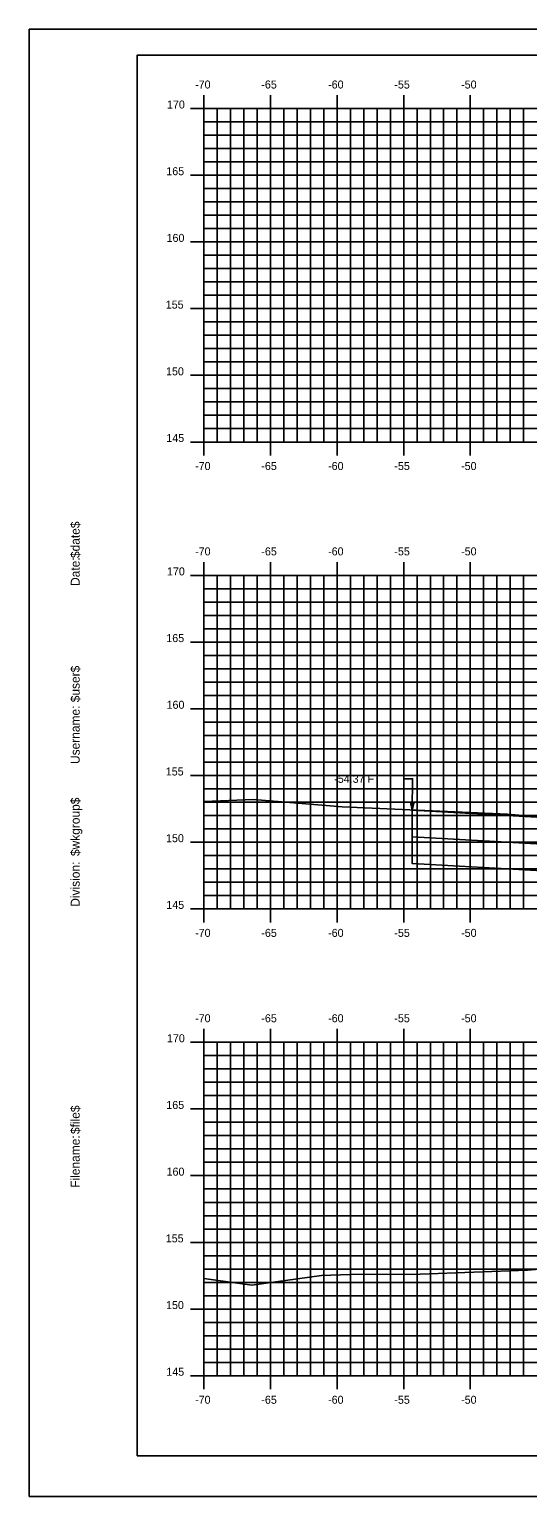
# Model space of a CAD drawing. Extents: x 1141202 to 1141372, y 608981 to 609091.
# Drawn here: x 1141202.4 to 1141239.8, y 608981.3 to 609091.3 of the extents above; entities that cross this region are included whole.
import ezdxf

# ---------------------------------------------------------------- set-up
doc = ezdxf.new("R2010")
doc.units = 0
for name, color, linetype in [('BORDER', 7, 'Continuous'), ('D_Text_Standard', 7, 'Continuous'), ('H_V ANNOTATION', 7, 'Continuous'), ('MAJOR', 7, 'Continuous'), ('MINOR', 7, 'Continuous'), ('PATTERNING', 7, 'Continuous'), ('PLOT BOUNDARY', 7, 'Continuous'), ('S_Roadway_Centerline', 7, 'Continuous')]:
    doc.layers.add(name, color=color, linetype=linetype)

msp = doc.modelspace()

# ---------------------------------------------------------------- linework, layer by layer
at = {"layer": 'BORDER'}
msp.add_lwpolyline([(1141210.51, 608984.34), (1141370.51, 608984.34), (1141370.51, 609089.34), (1141210.51, 609089.34)], close=True, dxfattribs=at)
at = {"layer": 'D_Text_Standard'}
msp.add_lwpolyline([(1141231.14, 609032.75), (1141231.18, 609035.09), (1141230.5, 609035.09)], dxfattribs=at)
msp.add_lwpolyline([(1141231.14, 609032.75), (1141231.01, 609033.34), (1141231.3, 609033.33)], close=True, dxfattribs=at)
at = {"layer": 'MAJOR'}
for p, q in [((1141215.51, 609086.34), (1141215.51, 609085.34)), ((1141220.51, 609086.34), (1141220.51, 609085.34)), ((1141225.51, 609086.34), (1141225.51, 609085.34)), ((1141230.51, 609086.34), (1141230.51, 609085.34)), ((1141235.51, 609086.34), (1141235.51, 609085.34)), ((1141214.51, 609085.34), (1141215.51, 609085.34)), ((1141215.51, 609085.34), (1141355.51, 609085.34)), ((1141215.51, 609060.34), (1141215.51, 609085.34)), ((1141215.51, 609060.34), (1141215.51, 609085.34)), ((1141215.51, 609085.34), (1141355.51, 609085.34)), ((1141220.51, 609060.34), (1141220.51, 609085.34)), ((1141225.51, 609060.34), (1141225.51, 609085.34)), ((1141230.51, 609060.34), (1141230.51, 609085.34)), ((1141235.51, 609060.34), (1141235.51, 609085.34)), ((1141214.51, 609080.34), (1141215.51, 609080.34)), ((1141215.51, 609080.34), (1141355.51, 609080.34)), ((1141214.51, 609075.34), (1141215.51, 609075.34)), ((1141215.51, 609075.34), (1141355.51, 609075.34)), ((1141214.51, 609070.34), (1141215.51, 609070.34)), ((1141215.51, 609070.34), (1141355.51, 609070.34)), ((1141214.51, 609065.34), (1141215.51, 609065.34)), ((1141215.51, 609065.34), (1141355.51, 609065.34)), ((1141214.51, 609060.34), (1141215.51, 609060.34)), ((1141215.51, 609060.34), (1141355.51, 609060.34)), ((1141215.51, 609060.34), (1141355.51, 609060.34)), ((1141215.51, 609059.33), (1141215.51, 609060.34)), ((1141220.51, 609059.33), (1141220.51, 609060.34)), ((1141225.51, 609059.33), (1141225.51, 609060.34)), ((1141230.51, 609059.33), (1141230.51, 609060.34)), ((1141235.51, 609059.33), (1141235.51, 609060.34)), ((1141215.51, 609051.34), (1141215.51, 609050.34)), ((1141220.51, 609051.34), (1141220.51, 609050.34)), ((1141225.51, 609051.34), (1141225.51, 609050.34)), ((1141230.51, 609051.34), (1141230.51, 609050.34)), ((1141235.51, 609051.34), (1141235.51, 609050.34)), ((1141214.51, 609050.34), (1141215.51, 609050.34)), ((1141215.51, 609050.34), (1141355.51, 609050.34)), ((1141215.51, 609025.34), (1141215.51, 609050.34)), ((1141215.51, 609025.34), (1141215.51, 609050.34)), ((1141215.51, 609050.34), (1141355.51, 609050.34)), ((1141220.51, 609025.34), (1141220.51, 609050.34)), ((1141225.51, 609025.34), (1141225.51, 609050.34)), ((1141230.51, 609025.34), (1141230.51, 609050.34)), ((1141235.51, 609025.34), (1141235.51, 609050.34)), ((1141214.51, 609045.34), (1141215.51, 609045.34)), ((1141215.51, 609045.34), (1141355.51, 609045.34)), ((1141214.51, 609040.34), (1141215.51, 609040.34)), ((1141215.51, 609040.34), (1141355.51, 609040.34)), ((1141214.51, 609035.34), (1141215.51, 609035.34)), ((1141215.51, 609035.34), (1141355.51, 609035.34)), ((1141214.51, 609030.34), (1141215.51, 609030.34)), ((1141215.51, 609030.34), (1141355.51, 609030.34)), ((1141214.51, 609025.34), (1141215.51, 609025.34)), ((1141215.51, 609025.34), (1141355.51, 609025.34)), ((1141215.51, 609025.34), (1141355.51, 609025.34)), ((1141215.51, 609024.33), (1141215.51, 609025.34)), ((1141220.51, 609024.33), (1141220.51, 609025.34)), ((1141225.51, 609024.33), (1141225.51, 609025.34)), ((1141230.51, 609024.33), (1141230.51, 609025.34)), ((1141235.51, 609024.33), (1141235.51, 609025.34)), ((1141215.51, 609016.34), (1141215.51, 609015.34)), ((1141220.51, 609016.34), (1141220.51, 609015.34)), ((1141225.51, 609016.34), (1141225.51, 609015.34)), ((1141230.51, 609016.34), (1141230.51, 609015.34)), ((1141235.51, 609016.34), (1141235.51, 609015.34)), ((1141214.51, 609015.34), (1141215.51, 609015.34)), ((1141215.51, 609015.34), (1141355.51, 609015.34)), ((1141215.51, 608990.34), (1141215.51, 609015.34)), ((1141215.51, 608990.34), (1141215.51, 609015.34)), ((1141215.51, 609015.34), (1141355.51, 609015.34)), ((1141220.51, 608990.34), (1141220.51, 609015.34)), ((1141225.51, 608990.34), (1141225.51, 609015.34)), ((1141230.51, 608990.34), (1141230.51, 609015.34)), ((1141235.51, 608990.34), (1141235.51, 609015.34)), ((1141214.51, 609010.34), (1141215.51, 609010.34)), ((1141215.51, 609010.34), (1141355.51, 609010.34)), ((1141214.51, 609005.34), (1141215.51, 609005.34)), ((1141215.51, 609005.34), (1141355.51, 609005.34)), ((1141214.51, 609000.34), (1141215.51, 609000.34)), ((1141215.51, 609000.34), (1141355.51, 609000.34)), ((1141214.51, 608995.34), (1141215.51, 608995.34)), ((1141215.51, 608995.34), (1141355.51, 608995.34)), ((1141214.51, 608990.34), (1141215.51, 608990.34)), ((1141215.51, 608990.34), (1141355.51, 608990.34)), ((1141215.51, 608990.34), (1141355.51, 608990.34)), ((1141215.51, 608989.33), (1141215.51, 608990.34)), ((1141220.51, 608989.33), (1141220.51, 608990.34)), ((1141225.51, 608989.33), (1141225.51, 608990.34)), ((1141230.51, 608989.33), (1141230.51, 608990.34)), ((1141235.51, 608989.33), (1141235.51, 608990.34))]:
    msp.add_line(p, q, dxfattribs=at)
at = {"layer": 'MINOR'}
for p, q in [((1141215.51, 609084.34), (1141355.51, 609084.34)), ((1141215.51, 609084.34), (1141216.52, 609084.34)), ((1141216.51, 609060.34), (1141216.51, 609085.34)), ((1141217.51, 609060.34), (1141217.51, 609085.34)), ((1141218.51, 609060.34), (1141218.51, 609085.34)), ((1141219.51, 609060.34), (1141219.51, 609085.34)), ((1141221.51, 609060.34), (1141221.51, 609085.34)), ((1141222.51, 609060.34), (1141222.51, 609085.34)), ((1141223.51, 609060.34), (1141223.51, 609085.34)), ((1141224.51, 609060.34), (1141224.51, 609085.34)), ((1141226.51, 609060.34), (1141226.51, 609085.34)), ((1141227.51, 609060.34), (1141227.51, 609085.34)), ((1141228.51, 609060.34), (1141228.51, 609085.34)), ((1141229.51, 609060.34), (1141229.51, 609085.34)), ((1141231.51, 609060.34), (1141231.51, 609085.34)), ((1141232.51, 609060.34), (1141232.51, 609085.34)), ((1141233.51, 609060.34), (1141233.51, 609085.34)), ((1141234.51, 609060.34), (1141234.51, 609085.34)), ((1141236.51, 609060.34), (1141236.51, 609085.34)), ((1141237.51, 609060.34), (1141237.51, 609085.34)), ((1141238.51, 609060.34), (1141238.51, 609085.34)), ((1141239.51, 609060.34), (1141239.51, 609085.34)), ((1141215.51, 609083.34), (1141355.51, 609083.34)), ((1141215.51, 609083.34), (1141216.52, 609083.34)), ((1141215.51, 609082.34), (1141355.51, 609082.34)), ((1141215.51, 609082.34), (1141216.52, 609082.34)), ((1141215.51, 609081.34), (1141355.51, 609081.34)), ((1141215.51, 609081.34), (1141216.52, 609081.34)), ((1141215.51, 609079.34), (1141355.51, 609079.34)), ((1141215.51, 609079.34), (1141216.52, 609079.34)), ((1141215.51, 609078.34), (1141355.51, 609078.34)), ((1141215.51, 609078.34), (1141216.52, 609078.34)), ((1141215.51, 609077.34), (1141355.51, 609077.34)), ((1141215.51, 609077.34), (1141216.52, 609077.34)), ((1141215.51, 609076.34), (1141355.51, 609076.34)), ((1141215.51, 609076.34), (1141216.52, 609076.34)), ((1141215.51, 609074.34), (1141355.51, 609074.34)), ((1141215.51, 609074.34), (1141216.52, 609074.34)), ((1141215.51, 609073.34), (1141355.51, 609073.34)), ((1141215.51, 609073.34), (1141216.52, 609073.34)), ((1141215.51, 609072.34), (1141355.51, 609072.34)), ((1141215.51, 609072.34), (1141216.52, 609072.34)), ((1141215.51, 609071.34), (1141355.51, 609071.34)), ((1141215.51, 609071.34), (1141216.52, 609071.34)), ((1141215.51, 609069.34), (1141355.51, 609069.34)), ((1141215.51, 609069.34), (1141216.52, 609069.34)), ((1141215.51, 609068.34), (1141355.51, 609068.34)), ((1141215.51, 609068.34), (1141216.52, 609068.34)), ((1141215.51, 609067.34), (1141355.51, 609067.34)), ((1141215.51, 609067.34), (1141216.52, 609067.34)), ((1141215.51, 609066.34), (1141355.51, 609066.34)), ((1141215.51, 609066.34), (1141216.52, 609066.34)), ((1141215.51, 609064.34), (1141355.51, 609064.34)), ((1141215.51, 609064.34), (1141216.52, 609064.34)), ((1141215.51, 609063.34), (1141355.51, 609063.34)), ((1141215.51, 609063.34), (1141216.52, 609063.34)), ((1141215.51, 609062.34), (1141355.51, 609062.34)), ((1141215.51, 609062.34), (1141216.52, 609062.34)), ((1141215.51, 609061.34), (1141355.51, 609061.34)), ((1141215.51, 609061.34), (1141216.52, 609061.34)), ((1141216.51, 609025.34), (1141216.51, 609050.34)), ((1141217.51, 609025.34), (1141217.51, 609050.34)), ((1141218.51, 609025.34), (1141218.51, 609050.34)), ((1141219.51, 609025.34), (1141219.51, 609050.34)), ((1141221.51, 609025.34), (1141221.51, 609050.34)), ((1141222.51, 609025.34), (1141222.51, 609050.34)), ((1141223.51, 609025.34), (1141223.51, 609050.34)), ((1141224.51, 609025.34), (1141224.51, 609050.34)), ((1141226.51, 609025.34), (1141226.51, 609050.34)), ((1141227.51, 609025.34), (1141227.51, 609050.34)), ((1141228.51, 609025.34), (1141228.51, 609050.34)), ((1141229.51, 609025.34), (1141229.51, 609050.34)), ((1141231.51, 609025.34), (1141231.51, 609050.34)), ((1141232.51, 609025.34), (1141232.51, 609050.34)), ((1141233.51, 609025.34), (1141233.51, 609050.34)), ((1141234.51, 609025.34), (1141234.51, 609050.34)), ((1141236.51, 609025.34), (1141236.51, 609050.34)), ((1141237.51, 609025.34), (1141237.51, 609050.34)), ((1141238.51, 609025.34), (1141238.51, 609050.34)), ((1141239.51, 609025.34), (1141239.51, 609050.34)), ((1141215.51, 609049.34), (1141355.51, 609049.34)), ((1141215.51, 609049.34), (1141216.52, 609049.34)), ((1141215.51, 609048.34), (1141355.51, 609048.34)), ((1141215.51, 609048.34), (1141216.52, 609048.34)), ((1141215.51, 609047.34), (1141355.51, 609047.34)), ((1141215.51, 609047.34), (1141216.52, 609047.34)), ((1141215.51, 609046.34), (1141355.51, 609046.34)), ((1141215.51, 609046.34), (1141216.52, 609046.34)), ((1141215.51, 609044.34), (1141355.51, 609044.34)), ((1141215.51, 609044.34), (1141216.52, 609044.34)), ((1141215.51, 609043.34), (1141355.51, 609043.34)), ((1141215.51, 609043.34), (1141216.52, 609043.34)), ((1141215.51, 609042.34), (1141355.51, 609042.34)), ((1141215.51, 609042.34), (1141216.52, 609042.34)), ((1141215.51, 609041.34), (1141355.51, 609041.34)), ((1141215.51, 609041.34), (1141216.52, 609041.34)), ((1141215.51, 609039.34), (1141355.51, 609039.34)), ((1141215.51, 609039.34), (1141216.52, 609039.34)), ((1141215.51, 609038.34), (1141355.51, 609038.34)), ((1141215.51, 609038.34), (1141216.52, 609038.34)), ((1141215.51, 609037.34), (1141355.51, 609037.34)), ((1141215.51, 609037.34), (1141216.52, 609037.34)), ((1141215.51, 609036.34), (1141355.51, 609036.34)), ((1141215.51, 609036.34), (1141216.52, 609036.34)), ((1141215.51, 609034.34), (1141355.51, 609034.34)), ((1141215.51, 609034.34), (1141216.52, 609034.34)), ((1141215.51, 609033.34), (1141355.51, 609033.34)), ((1141215.51, 609033.34), (1141216.52, 609033.34)), ((1141215.51, 609032.34), (1141355.51, 609032.34)), ((1141215.51, 609032.34), (1141216.52, 609032.34)), ((1141215.51, 609031.34), (1141355.51, 609031.34)), ((1141215.51, 609031.34), (1141216.52, 609031.34)), ((1141215.51, 609029.34), (1141355.51, 609029.34)), ((1141215.51, 609029.34), (1141216.52, 609029.34)), ((1141215.51, 609028.34), (1141355.51, 609028.34)), ((1141215.51, 609028.34), (1141216.52, 609028.34)), ((1141215.51, 609027.34), (1141355.51, 609027.34)), ((1141215.51, 609027.34), (1141216.52, 609027.34)), ((1141215.51, 609026.34), (1141355.51, 609026.34)), ((1141215.51, 609026.34), (1141216.52, 609026.34)), ((1141216.51, 608990.34), (1141216.51, 609015.34)), ((1141217.51, 608990.34), (1141217.51, 609015.34)), ((1141218.51, 608990.34), (1141218.51, 609015.34)), ((1141219.51, 608990.34), (1141219.51, 609015.34)), ((1141221.51, 608990.34), (1141221.51, 609015.34)), ((1141222.51, 608990.34), (1141222.51, 609015.34)), ((1141223.51, 608990.34), (1141223.51, 609015.34)), ((1141224.51, 608990.34), (1141224.51, 609015.34)), ((1141226.51, 608990.34), (1141226.51, 609015.34)), ((1141227.51, 608990.34), (1141227.51, 609015.34)), ((1141228.51, 608990.34), (1141228.51, 609015.34)), ((1141229.51, 608990.34), (1141229.51, 609015.34)), ((1141231.51, 608990.34), (1141231.51, 609015.34)), ((1141232.51, 608990.34), (1141232.51, 609015.34)), ((1141233.51, 608990.34), (1141233.51, 609015.34)), ((1141234.51, 608990.34), (1141234.51, 609015.34)), ((1141236.51, 608990.34), (1141236.51, 609015.34)), ((1141237.51, 608990.34), (1141237.51, 609015.34)), ((1141238.51, 608990.34), (1141238.51, 609015.34)), ((1141239.51, 608990.34), (1141239.51, 609015.34)), ((1141215.51, 609014.34), (1141355.51, 609014.34)), ((1141215.51, 609014.34), (1141216.52, 609014.34)), ((1141215.51, 609013.34), (1141355.51, 609013.34)), ((1141215.51, 609013.34), (1141216.52, 609013.34)), ((1141215.51, 609012.34), (1141355.51, 609012.34)), ((1141215.51, 609012.34), (1141216.52, 609012.34)), ((1141215.51, 609011.34), (1141355.51, 609011.34)), ((1141215.51, 609011.34), (1141216.52, 609011.34)), ((1141215.51, 609009.34), (1141355.51, 609009.34)), ((1141215.51, 609009.34), (1141216.52, 609009.34)), ((1141215.51, 609008.34), (1141355.51, 609008.34)), ((1141215.51, 609008.34), (1141216.52, 609008.34)), ((1141215.51, 609007.34), (1141355.51, 609007.34)), ((1141215.51, 609007.34), (1141216.52, 609007.34)), ((1141215.51, 609006.34), (1141355.51, 609006.34)), ((1141215.51, 609006.34), (1141216.52, 609006.34)), ((1141215.51, 609004.34), (1141355.51, 609004.34)), ((1141215.51, 609004.34), (1141216.52, 609004.34)), ((1141215.51, 609003.34), (1141355.51, 609003.34)), ((1141215.51, 609003.34), (1141216.52, 609003.34)), ((1141215.51, 609002.34), (1141355.51, 609002.34)), ((1141215.51, 609002.34), (1141216.52, 609002.34)), ((1141215.51, 609001.34), (1141355.51, 609001.34)), ((1141215.51, 609001.34), (1141216.52, 609001.34)), ((1141215.51, 608999.34), (1141355.51, 608999.34)), ((1141215.51, 608999.34), (1141216.52, 608999.34)), ((1141215.51, 608998.34), (1141355.51, 608998.34)), ((1141215.51, 608998.34), (1141216.52, 608998.34)), ((1141215.51, 608997.34), (1141355.51, 608997.34)), ((1141215.51, 608997.34), (1141216.52, 608997.34)), ((1141215.51, 608996.34), (1141355.51, 608996.34)), ((1141215.51, 608996.34), (1141216.52, 608996.34)), ((1141215.51, 608994.34), (1141355.51, 608994.34)), ((1141215.51, 608994.34), (1141216.52, 608994.34)), ((1141215.51, 608993.34), (1141355.51, 608993.34)), ((1141215.51, 608993.34), (1141216.52, 608993.34)), ((1141215.51, 608992.34), (1141355.51, 608992.34)), ((1141215.51, 608992.34), (1141216.52, 608992.34)), ((1141215.51, 608991.34), (1141355.51, 608991.34)), ((1141215.51, 608991.34), (1141216.52, 608991.34))]:
    msp.add_line(p, q, dxfattribs=at)
at = {"layer": 'PATTERNING'}
for points in [[(1141240.95, 609032.19), (1141231.14, 609032.75), (1141231.14, 609030.75), (1141240.93, 609030.19)], [(1141240.95, 609030.19), (1141231.14, 609030.75), (1141231.14, 609028.75), (1141240.93, 609028.19)]]:
    msp.add_lwpolyline(points, close=True, dxfattribs=at)
at = {"layer": 'PLOT BOUNDARY'}
msp.add_lwpolyline([(1141202.42, 608981.28), (1141372.42, 608981.28), (1141372.42, 609091.28), (1141202.42, 609091.28)], close=True, dxfattribs=at)
at = {"layer": 'S_Roadway_Centerline'}
for points in [[(1141215.51, 609033.39), (1141219.23, 609033.54), (1141225.89, 609032.98), (1141238.3, 609032.43), (1141240.85, 609032.21)], [(1141215.51, 608997.63), (1141219.11, 608997.12), (1141224.35, 608997.85), (1141226.46, 608997.92), (1141231.75, 608997.96), (1141239.79, 608998.25), (1141245.23, 608998.7)]]:
    msp.add_lwpolyline(points, dxfattribs=at)

# ---------------------------------------------------------------- texts
at = {"layer": 'BORDER'}
for s, p in [('$date$', (1141206.2, 609051.64)), ('Date:', (1141206.2, 609049.55)), ('$user$', (1141206.2, 609040.83)), ('Username:', (1141206.2, 609036.2)), ('$wkgroup$', (1141206.2, 609029.3)), ('Division:', (1141206.2, 609025.5)), ('$file$', (1141206.2, 609008.46)), ('Filename:', (1141206.2, 609004.43))]:
    msp.add_text(s, height=0.67, rotation=90, dxfattribs=at).set_placement(p)
at = {"layer": 'D_Text_Standard'}
msp.add_text('-54.37 FT', height=0.6, dxfattribs=at).set_placement((1141225.3, 609034.79))
at = {"layer": 'H_V ANNOTATION'}
for s, p in [('-70', (1141214.86, 609086.84)), ('-65', (1141219.83, 609086.84)), ('-60', (1141224.84, 609086.84)), ('-55', (1141229.81, 609086.84)), ('-50', (1141234.82, 609086.84)), ('170', (1141212.75, 609085.34)), ('165', (1141212.7, 609080.34)), ('160', (1141212.72, 609075.34)), ('155', (1141212.66, 609070.34)), ('150', (1141212.68, 609065.34)), ('145', (1141212.7, 609060.34)), ('-70', (1141214.86, 609058.24)), ('-65', (1141219.83, 609058.24)), ('-60', (1141224.84, 609058.24)), ('-55', (1141229.81, 609058.24)), ('-50', (1141234.82, 609058.24)), ('-70', (1141214.86, 609051.84)), ('-65', (1141219.83, 609051.84)), ('-60', (1141224.84, 609051.84)), ('-55', (1141229.81, 609051.84)), ('-50', (1141234.82, 609051.84)), ('170', (1141212.75, 609050.34)), ('165', (1141212.7, 609045.34)), ('160', (1141212.72, 609040.34)), ('155', (1141212.66, 609035.34)), ('150', (1141212.68, 609030.34)), ('145', (1141212.7, 609025.34)), ('-70', (1141214.86, 609023.24)), ('-65', (1141219.83, 609023.24)), ('-60', (1141224.84, 609023.24)), ('-55', (1141229.81, 609023.24)), ('-50', (1141234.82, 609023.24)), ('-70', (1141214.86, 609016.84)), ('-65', (1141219.83, 609016.84)), ('-60', (1141224.84, 609016.84)), ('-55', (1141229.81, 609016.84)), ('-50', (1141234.82, 609016.84)), ('170', (1141212.75, 609015.34)), ('165', (1141212.7, 609010.34)), ('160', (1141212.72, 609005.34)), ('155', (1141212.66, 609000.34)), ('150', (1141212.68, 608995.34)), ('145', (1141212.7, 608990.34)), ('-70', (1141214.86, 608988.24)), ('-65', (1141219.83, 608988.24)), ('-60', (1141224.84, 608988.24)), ('-55', (1141229.81, 608988.24)), ('-50', (1141234.82, 608988.24))]:
    msp.add_text(s, height=0.6, dxfattribs=at).set_placement(p)
at = {"layer": 'MAJOR'}
for p in [(1141215.51, 609060.34), (1141215.51, 609025.34), (1141215.51, 608990.34)]:
    msp.add_text('-', height=0.006, dxfattribs=at).set_placement(p)

doc.saveas('drawing.dxf')
